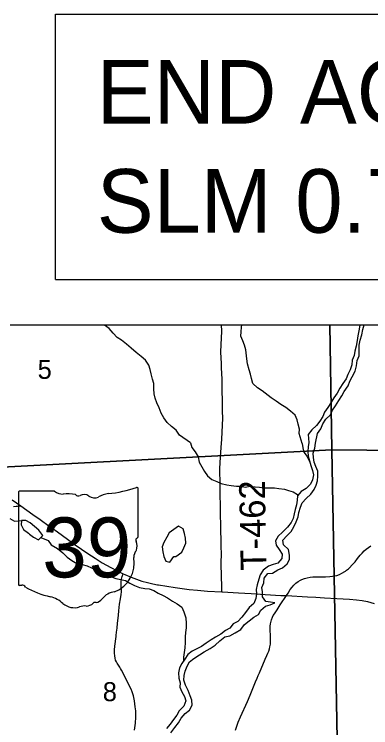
# Model space of a CAD drawing. Extents: x 0 to 34, y 0 to 22.
# Drawn here: x 5.429 to 6.214, y 15.182 to 16.75 of the extents above; entities that cross this region are included whole.
import ezdxf

# ---------------------------------------------------------------- set-up
doc = ezdxf.new("R2010")
doc.units = 0
for name, color, linetype in [('GM_X_County_Road', 7, 'Continuous'), ('GM_X_County_Road_Text', 7, 'Continuous'), ('GM_X_Interchange_Ramps', 7, 'Continuous'), ('GM_X_Major_River_Text', 7, 'Continuous'), ('GM_X_Minor_River_Text', 7, 'Continuous'), ('GM_X_State_Location', 7, 'Continuous'), ('GM_X_State_Route', 7, 'Continuous'), ('GM_X_State_Shield', 7, 'Continuous'), ('GM_X_Township_Text', 7, 'Continuous'), ('SH_Text', 7, 'Continuous')]:
    doc.layers.add(name, color=color, linetype=linetype)

msp = doc.modelspace()

# ---------------------------------------------------------------- linework, layer by layer
at = {"layer": 'GM_X_County_Road'}
for p, q in [((5.7016, 15.6021), (5.7016, 15.7067)), ((5.4379, 15.6983), (5.4379, 15.4982)), ((5.5177, 15.7018), (5.4405, 15.7018)), ((5.7015, 15.6021), (5.7016, 15.6021))]:
    msp.add_line(p, q, dxfattribs=at)
for points in [[(5.4243, 15.6831), (5.4432, 15.6697)], [(5.4432, 15.6697), (5.4698, 15.6507), (5.4856, 15.6394), (5.5059, 15.6251), (5.5186, 15.616), (5.5318, 15.6066), (5.5632, 15.5839), (5.5912, 15.5645), (5.6067, 15.5543), (5.6227, 15.5446), (5.6417, 15.534), (5.6555, 15.5269), (5.6689, 15.5204)], [(5.6689, 15.5204), (5.6722, 15.5188), (5.6861, 15.5126), (5.6982, 15.5081), (5.71, 15.5041), (5.722, 15.5008), (5.7341, 15.498), (5.7445, 15.4961)], [(5.7445, 15.4961), (5.7464, 15.4957), (5.7833, 15.4901), (5.8141, 15.4859), (5.8326, 15.4839), (5.8543, 15.4822), (5.8861, 15.4803)], [(5.8861, 15.4803), (5.8876, 15.4802), (5.9226, 15.4783), (5.9505, 15.4766), (5.9815, 15.4748), (6.0155, 15.4728), (6.0278, 15.4721)], [(6.0278, 15.4721), (6.0743, 15.4696), (6.0925, 15.4686)], [(6.0925, 15.4686), (6.1117, 15.4674), (6.1389, 15.466), (6.1668, 15.4641), (6.1824, 15.4629), (6.1945, 15.4614), (6.2066, 15.4591), (6.2214, 15.4548)]]:
    msp.add_lwpolyline(points, dxfattribs=at)
for centre, radius, start, end in [((5.6076, 15.9746), 0.2796, 275.8445, 288.9065), ((5.6986, 15.7072), 0.00294, 351.8621, 97.738), ((5.4409, 15.6988), 0.00305, 98.1301, 188.1301), ((5.5361, 15.725), 0.0296, 231.6195, 271.1119), ((5.5459, 15.5894), 0.1064, 80.4867, 94.9883), ((5.5701, 15.6998), 0.00855, 219.7921, 297.1024), ((5.5826, 15.6767), 0.0178, 54.4667, 119.1411), ((5.6056, 15.7084), 0.0214, 233.8562, 294.8282), ((5.6433, 15.6407), 0.0563, 97.3462, 120.7689), ((5.7009, 15.5944), 0.00454, 107.944, 210.337), ((5.6984, 15.6016), 0.00314, 289.6038, 7.7341), ((5.672, 15.5811), 0.0273, 340.033, 23.6496), ((5.7121, 15.5582), 0.0198, 136.8065, 186.9296), ((5.6233, 15.5449), 0.0699, 292.3089, 8.9858), ((5.4409, 15.4978), 0.00308, 171.9584, 258.3066), ((5.4414, 15.5183), 0.0235, 267.339, 280.6039), ((5.4462, 15.4867), 0.00848, 29.7484, 93.2717), ((5.5533, 15.6665), 0.2019, 240.4129, 257.1985), ((5.4931, 15.4083), 0.0632, 47.1842, 75.836), ((5.6528, 15.442), 0.0383, 94.4031, 142.5768), ((5.5614, 15.4857), 0.0401, 230.7004, 286.2918), ((5.5875, 15.4707), 0.0214, 268.777, 315.5493), ((5.6068, 15.4513), 0.00601, 65.7517, 132.6484), ((5.6043, 15.4788), 0.0226, 282.8732, 323.2771), ((5.5846, 15.4165), 0.0329, 85.6951, 111.2099)]:
    msp.add_arc(centre, radius, start, end, dxfattribs=at)
at = {"layer": 'GM_X_County_Road_Text'}
for points in [[(5.8171, 15.8079), (5.7929, 15.8252), (5.7854, 15.8359), (5.7753, 15.8443), (5.7655, 15.8528), (5.7584, 15.8631), (5.7524, 15.8737), (5.7476, 15.8848), (5.7427, 15.8962), (5.739, 15.9065), (5.7372, 15.916), (5.7362, 15.927), (5.7363, 15.9387), (5.7329, 15.9482), (5.7304, 15.9596), (5.7278, 15.9695), (5.7248, 15.979), (5.7181, 15.9897), (5.7079, 15.9978), (5.697, 16.007), (5.6865, 16.0162), (5.6763, 16.025), (5.665, 16.0338), (5.6552, 16.0396), (5.6466, 16.0491), (5.6379, 16.0594), (5.6278, 16.0671), (5.6275, 16.0674)], [(6.063, 15.8069), (6.056, 15.8285), (6.0565, 15.8383), (6.0535, 15.8494), (6.0513, 15.8589), (6.0469, 15.8688), (6.0367, 15.8776), (6.0265, 15.886), (6.0156, 15.8926), (6.0054, 15.8995), (5.9941, 15.9068), (5.9745, 15.9221), (5.9644, 15.9287), (5.9538, 15.9383), (5.9513, 15.9493), (5.9491, 15.9592), (5.9457, 15.9687), (5.942, 15.9816), (5.9406, 15.993), (5.9385, 16.0127), (5.9359, 16.0226), (5.9319, 16.0321), (5.9278, 16.0428), (5.9282, 16.0523), (5.9291, 16.0621), (5.9297, 16.0674)], [(5.8171, 15.8079), (5.8198, 15.7981), (5.8271, 15.7883), (5.8337, 15.7773), (5.8361, 15.7659), (5.8418, 15.7557), (5.848, 15.7452), (5.8545, 15.7354), (5.8641, 15.7275), (5.8747, 15.723), (5.8846, 15.7185), (5.8968, 15.716), (5.9066, 15.7142), (5.918, 15.7127), (5.9275, 15.7128), (5.9377, 15.711), (5.9476, 15.713), (5.9589, 15.7112), (5.9684, 15.7105), (5.9783, 15.7091), (5.9889, 15.7095), (6.0014, 15.7089), (6.0113, 15.7075), (6.0234, 15.706), (6.0329, 15.7031), (6.0432, 15.7005), (6.0527, 15.6945), (6.0542, 15.6933)], [(6.063, 15.8069), (6.0639, 15.7974), (6.0662, 15.7876), (6.0735, 15.7778), (6.0788, 15.7673)], [(5.4194, 15.6418), (5.4295, 15.6362), (5.4447, 15.6375)], [(5.4874, 15.5999), (5.5034, 15.5936), (5.5103, 15.5838), (5.524, 15.5756), (5.5355, 15.5665), (5.5451, 15.5564), (5.5553, 15.5493), (5.5668, 15.5429), (5.5785, 15.5407), (5.5892, 15.5374), (5.5991, 15.5333), (5.6097, 15.5285), (5.6215, 15.5244), (5.6314, 15.5173), (5.6428, 15.5132), (5.6523, 15.5095), (5.6736, 15.5051), (5.6835, 15.4995), (5.6934, 15.4943), (5.7044, 15.4898), (5.7162, 15.4876), (5.726, 15.4869), (5.7359, 15.4832), (5.7455, 15.4776), (5.7565, 15.4724), (5.766, 15.4672), (5.7774, 15.4601), (5.7877, 15.4544), (5.7976, 15.4469), (5.8023, 15.4367), (5.8062, 15.4231), (5.8071, 15.411), (5.8075, 15.4015), (5.8061, 15.3912), (5.8051, 15.3814), (5.8048, 15.3688), (5.8045, 15.3575), (5.8027, 15.3472), (5.8013, 15.337), (5.8014, 15.3285)]]:
    msp.add_lwpolyline(points, dxfattribs=at)
at = {"layer": 'GM_X_Interchange_Ramps'}
for points in [[(5.8847, 15.549), (5.8848, 15.5597), (5.8843, 15.5845), (5.8834, 15.6249), (5.8831, 15.6528), (5.8829, 15.6683), (5.8825, 15.6962), (5.882, 15.7179), (5.8818, 15.7303), (5.8817, 15.7365), (5.8816, 15.7427), (5.8817, 15.7519), (5.8831, 15.7765), (5.8844, 15.7979), (5.8856, 15.8163), (5.8865, 15.8316), (5.8873, 15.847), (5.8878, 15.8624), (5.8876, 15.8778), (5.8874, 15.8871), (5.8872, 15.8964), (5.887, 15.9057), (5.8868, 15.918), (5.8867, 15.9272), (5.8867, 15.9334), (5.8863, 15.948), (5.8859, 15.9608), (5.8854, 15.9731), (5.8849, 15.9829), (5.8842, 15.9953), (5.8837, 16.0076), (5.8841, 16.0242), (5.8851, 16.038), (5.8857, 16.0536), (5.8854, 16.0674)], [(5.4271, 15.6685), (5.4332, 15.6688), (5.4362, 15.669), (5.4432, 15.6697)], [(6.1536, 15.5235), (6.1553, 15.5246), (6.1578, 15.5262), (6.1602, 15.5278), (6.1648, 15.5313), (6.1669, 15.5332), (6.173, 15.5398), (6.179, 15.5467), (6.1848, 15.5539), (6.1906, 15.5612), (6.1947, 15.5658), (6.199, 15.5703), (6.2037, 15.5744), (6.2086, 15.5781), (6.2138, 15.5814)], [(5.8861, 15.4803), (5.8857, 15.4914), (5.8855, 15.4945), (5.8848, 15.5131), (5.8847, 15.5442), (5.8847, 15.549)], [(5.6934, 15.1767), (5.6955, 15.1918), (5.6967, 15.205), (5.6968, 15.2077), (5.6968, 15.2108), (5.6965, 15.2186), (5.6953, 15.2275), (5.6935, 15.241), (5.6913, 15.2515), (5.6887, 15.2605), (5.6879, 15.2625), (5.6871, 15.2646), (5.6829, 15.274), (5.6652, 15.3082), (5.6631, 15.3117), (5.6614, 15.3146), (5.6552, 15.3237), (5.6536, 15.3266), (5.6521, 15.3305), (5.6509, 15.3349), (5.65, 15.3401), (5.6493, 15.3456), (5.6493, 15.3533), (5.6502, 15.3612), (5.6517, 15.3716), (5.6525, 15.3776), (5.6529, 15.3816), (5.6534, 15.3867), (5.6537, 15.3896), (5.6542, 15.3925), (5.6546, 15.3956), (5.6554, 15.4016), (5.6565, 15.4107), (5.6581, 15.4292), (5.659, 15.4384), (5.6607, 15.4534), (5.6629, 15.4653), (5.6645, 15.4745), (5.6648, 15.4807), (5.6641, 15.4962), (5.6643, 15.5039), (5.6647, 15.5084), (5.6655, 15.5114), (5.6666, 15.5143), (5.6689, 15.5204)], [(6.0278, 15.4721), (6.0315, 15.4777), (6.0365, 15.4855), (6.0403, 15.4905), (6.0444, 15.4951), (6.049, 15.4993), (6.054, 15.503), (6.0592, 15.5063), (6.062, 15.5077), (6.0678, 15.5099), (6.0738, 15.5116), (6.0799, 15.5127), (6.0861, 15.5134), (6.0954, 15.5137), (6.114, 15.5138), (6.1233, 15.5141), (6.1295, 15.5146), (6.1345, 15.5155), (6.1386, 15.5167), (6.1445, 15.5187), (6.1501, 15.5214), (6.1527, 15.523), (6.1536, 15.5235)], [(5.989, 15.3498), (5.9906, 15.3551), (5.9917, 15.3595), (5.9927, 15.3655), (5.9933, 15.3716), (5.9933, 15.3778), (5.9931, 15.3809), (5.9926, 15.3871), (5.9921, 15.3931), (5.992, 15.399), (5.9923, 15.4048), (5.9929, 15.4103), (5.9934, 15.4131), (5.9942, 15.4161), (5.9951, 15.419), (5.9975, 15.4248), (5.9991, 15.4283), (6.0018, 15.4324), (6.0073, 15.4409), (6.0143, 15.452), (6.0278, 15.4721)], [(5.9159, 15.1765), (5.9186, 15.1854), (5.922, 15.1941), (5.9269, 15.2055), (5.9421, 15.2392), (5.9481, 15.2535), (5.9597, 15.2823), (5.9633, 15.2908), (5.9658, 15.2964), (5.9684, 15.3026), (5.9812, 15.3324), (5.985, 15.3405), (5.9874, 15.346), (5.989, 15.3498)]]:
    msp.add_lwpolyline(points, dxfattribs=at)
at = {"layer": 'GM_X_Minor_River_Text'}
for points in [[(5.4732, 15.6245), (5.4637, 15.632), (5.4541, 15.6372), (5.4447, 15.6375), (5.4444, 15.628), (5.4494, 15.6178), (5.4601, 15.6092), (5.4624, 15.6073)], [(5.4624, 15.6073), (5.4715, 15.6009), (5.4826, 15.5946), (5.4916, 15.6045), (5.4831, 15.6158), (5.4732, 15.6245)], [(5.801, 15.6188), (5.7907, 15.6248), (5.7798, 15.6175), (5.77, 15.6102), (5.7644, 15.6007), (5.7585, 15.5893), (5.7548, 15.5797), (5.7556, 15.5688), (5.758, 15.5585), (5.7623, 15.5476), (5.7717, 15.5461), (5.7803, 15.5583), (5.7845, 15.558)], [(5.7845, 15.558), (5.7977, 15.568), (5.8025, 15.5775), (5.8062, 15.5878), (5.8057, 15.5984), (5.8034, 15.609), (5.801, 15.6188)]]:
    msp.add_lwpolyline(points, dxfattribs=at)
at = {"layer": 'GM_X_State_Route'}
for points in [[(6.1232, 16.0674), (6.1276, 15.7926), (5.1364, 15.7406), (5.1198, 16.7337), (5.2028, 16.735)], [(7.124, 16.0674), (7.1265, 15.7834), (6.1276, 15.7926), (6.1232, 16.0674)]]:
    msp.add_lwpolyline(points, dxfattribs=at)
for points in [[(5.1364, 15.7406), (6.1276, 15.7926), (6.1462, 14.7998), (5.7574, 14.7844), (5.149, 14.7448)], [(6.1276, 15.7926), (7.1265, 15.7834), (7.1266, 15.779), (7.1286, 14.7729), (6.1462, 14.7998)]]:
    msp.add_lwpolyline(points, close=True, dxfattribs=at)
at = {"layer": 'GM_X_State_Shield'}
for points in [[(6.1897, 16.0674), (6.1895, 16.0669), (6.1871, 16.0545), (6.1851, 16.0435), (6.1835, 16.0329), (6.1812, 16.0208), (6.1784, 16.0098), (6.1768, 15.9999), (6.1729, 15.9897), (6.1717, 15.9795), (6.1682, 15.9685), (6.1632, 15.9587), (6.1597, 15.9485), (6.1524, 15.9387), (6.1455, 15.9282), (6.1398, 15.9176), (6.1321, 15.9071), (6.1259, 15.8961), (6.119, 15.8859), (6.1117, 15.8758), (6.1079, 15.8659), (6.1017, 15.8561), (6.0941, 15.846), (6.0841, 15.837), (6.0761, 15.8264), (6.0774, 15.8085)], [(6.0918, 15.8071), (6.0966, 15.8285), (6.1035, 15.8387), (6.1081, 15.85), (6.1146, 15.8598), (6.1249, 15.8696), (6.1292, 15.8798), (6.1361, 15.8896), (6.1434, 15.9013), (6.1503, 15.9111), (6.1553, 15.9209), (6.1638, 15.9337), (6.1673, 15.9435), (6.1726, 15.9533), (6.1792, 15.9654), (6.1819, 15.9775), (6.1839, 15.9889), (6.1882, 15.9995), (6.1883, 16.0108), (6.188, 16.0226), (6.19, 16.034), (6.1943, 16.0453), (6.1962, 16.0574), (6.1989, 16.0674)], [(6.0774, 15.8085), (6.0756, 15.799), (6.0753, 15.7888), (6.0762, 15.7789), (6.0785, 15.7687), (6.0817, 15.7581), (6.0852, 15.7475), (6.0875, 15.7377), (6.0857, 15.7267), (6.0809, 15.7171), (6.0711, 15.7076), (6.0606, 15.701), (6.0527, 15.6915), (6.0517, 15.682), (6.0499, 15.6717), (6.0469, 15.6618), (6.0451, 15.6523), (6.0425, 15.6421), (6.0388, 15.6326), (6.0302, 15.6226), (6.0197, 15.6115), (6.0096, 15.6027), (6.004, 15.5928), (6.0052, 15.5833), (6.0121, 15.5735), (6.0183, 15.5633), (6.018, 15.5539), (6.0093, 15.5439), (5.9988, 15.5404), (5.9882, 15.5373), (5.9765, 15.5285), (5.9702, 15.5182), (5.9672, 15.5087), (5.9639, 15.4961), (5.9617, 15.4855), (5.9622, 15.476), (5.9608, 15.4657), (5.956, 15.4547), (5.9462, 15.4463), (5.9376, 15.4352), (5.9301, 15.4249), (5.9207, 15.4153), (5.9109, 15.4103), (5.9034, 15.4008), (5.8936, 15.3958), (5.8838, 15.3873), (5.8721, 15.3808), (5.8623, 15.375), (5.8514, 15.3677), (5.8413, 15.3604), (5.8311, 15.355), (5.8205, 15.35), (5.8107, 15.3427), (5.804, 15.3324), (5.7976, 15.3229), (5.7928, 15.3134), (5.7906, 15.3027), (5.7911, 15.291), (5.7942, 15.2807), (5.7932, 15.2709), (5.7978, 15.2607), (5.8036, 15.2505), (5.8067, 15.2406), (5.8019, 15.2288), (5.7921, 15.2189), (5.7865, 15.2094), (5.7791, 15.1998), (5.7719, 15.1899), (5.7641, 15.1803)], [(5.7736, 15.1702), (5.7826, 15.1824), (5.7905, 15.1923), (5.7961, 15.203), (5.8051, 15.2129), (5.8149, 15.2202), (5.8208, 15.2313), (5.82, 15.2423), (5.8161, 15.2521), (5.8114, 15.2634), (5.8057, 15.2751), (5.8021, 15.2865), (5.8032, 15.2964), (5.8054, 15.3063), (5.8098, 15.3169), (5.8143, 15.3264), (5.8244, 15.3337), (5.8365, 15.3418), (5.8467, 15.3487), (5.8602, 15.356), (5.8712, 15.3633), (5.8813, 15.3729), (5.8922, 15.3813), (5.9036, 15.3841), (5.9149, 15.3906), (5.9273, 15.3976), (5.9359, 15.4086), (5.9457, 15.4167), (5.9562, 15.4247), (5.9668, 15.4309), (5.972, 15.4404), (5.9822, 15.4492), (5.9924, 15.4516), (6.0026, 15.4562), (5.9927, 15.4577), (5.9824, 15.4591), (5.9755, 15.4693), (5.9751, 15.4803), (5.9738, 15.4898), (5.9783, 15.5), (5.9793, 15.5107), (5.9872, 15.5206), (5.9974, 15.5214), (6.0091, 15.5287), (6.0193, 15.5334), (6.0294, 15.5422), (6.0347, 15.5517), (6.0349, 15.5612), (6.0322, 15.5737), (6.0219, 15.5835), (6.0199, 15.5941), (6.0289, 15.604), (6.0386, 15.6132), (6.0446, 15.6231), (6.0491, 15.6345), (6.0535, 15.6452), (6.0553, 15.6551), (6.059, 15.6665), (6.0623, 15.676), (6.0717, 15.6856), (6.0815, 15.6951), (6.089, 15.7054), (6.0934, 15.7153), (6.0967, 15.7249), (6.097, 15.7351), (6.0969, 15.7457), (6.093, 15.7559), (6.0888, 15.7658), (6.0876, 15.776), (6.0867, 15.7855), (6.0904, 15.7965), (6.0918, 15.8071)]]:
    msp.add_lwpolyline(points, dxfattribs=at)
at = {"layer": 'SH_Text'}
for p, q in [((5.5199, 16.7504), (7.4483, 16.7504)), ((5.5199, 16.1674), (5.5199, 16.7504)), ((5.5199, 16.1674), (7.4483, 16.1674)), ((5.4199, 16.0674), (7.5483, 16.0674))]:
    msp.add_line(p, q, dxfattribs=at)

# ---------------------------------------------------------------- texts
at = {"layer": 'GM_X_County_Road'}
msp.add_text('39', height=0.13184, dxfattribs=at).set_placement((5.4905, 15.5123))
at = {"layer": 'GM_X_Major_River_Text'}
for s in ['s', 'r']:
    msp.add_text(s, height=0.000189, dxfattribs=at).set_placement((5.5668, 15.585))
msp.add_text('39', height=0.000189, rotation=0, dxfattribs=at).set_placement((5.5191, 15.5712))
at = {"layer": 'GM_X_State_Location'}
for s, p in [('5', (5.4803, 15.9487)), ('8', (5.6237, 15.2401))]:
    msp.add_text(s, height=0.0419, rotation=0, dxfattribs=at).set_placement(p)
at = {"layer": 'GM_X_Township_Text'}
msp.add_text('T-462', height=0.05682, rotation=91.1242, dxfattribs=at).set_placement((5.9843, 15.5277))
at = {"layer": 'SH_Text'}
for s, p in [('END ACQUISITION', (5.6106, 16.51)), ('SLM 0.73', (5.6106, 16.27))]:
    msp.add_text(s, height=0.14, dxfattribs=at).set_placement(p)

doc.saveas('drawing.dxf')
